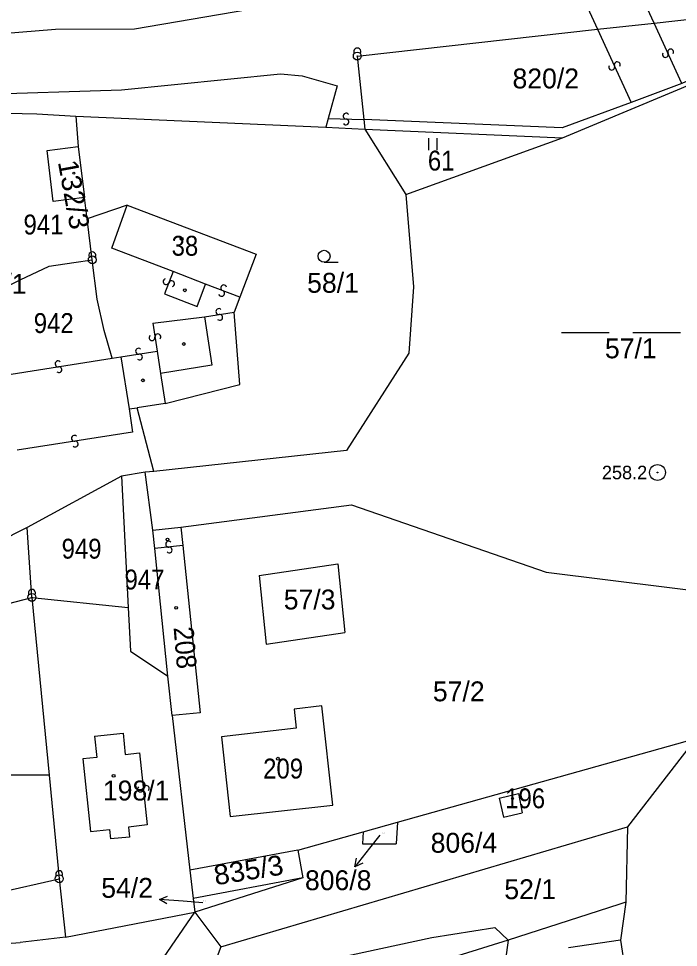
# Model space of a CAD drawing. Extents: x -680102 to -677253, y -1007548 to -1006096.
# Drawn here: x -679840 to -679757, y -1007209.6 to -1007092.8 of the extents above; entities that cross this region are included whole.
import ezdxf
from ezdxf.enums import TextEntityAlignment as Align

# ---------------------------------------------------------------- set-up
doc = ezdxf.new("R2010")
doc.units = 0
for name, color, linetype, lineweight in [('1', 7, 'Continuous', 25), ('16', 7, 'Continuous', 25), ('24', 7, 'Continuous', 25), ('25', 7, 'Continuous', 25), ('4', 7, 'Continuous', 25)]:
    doc.layers.add(name, color=color, linetype=linetype, lineweight=lineweight)
for name, color, linetype in [('17', 7, 'Continuous'), ('18', 7, 'Continuous'), ('19', 7, 'Continuous')]:
    doc.layers.add(name, color=color, linetype=linetype)

msp = doc.modelspace()

# ---------------------------------------------------------------- linework, layer by layer
at = {"layer": '1'}
for p, q in [((-679771.61, -1007107.84), (-679749.26, -1007098.51)), ((-679832.79, -1007105.1), (-679832.48, -1007108.92)), ((-679796.44, -1007106.73), (-679771.61, -1007107.84)), ((-679791.3, -1007114.95), (-679790.34, -1007126.57)), ((-679826.31, -1007116.31), (-679831.35, -1007118.02)), ((-679826.31, -1007116.31), (-679810.11, -1007122.46)), ((-679810.11, -1007122.46), (-679812.17, -1007127.87)), ((-679812.17, -1007127.87), (-679812.88, -1007129.74)), ((-679812.17, -1007138.86), (-679812.88, -1007129.74)), ((-679828.21, -1007135.56), (-679829.22, -1007132.08)), ((-679821.54, -1007141.26), (-679812.17, -1007138.86)), ((-679821.54, -1007141.26), (-679825.07, -1007141.78)), ((-679826.07, -1007141.93), (-679825.07, -1007141.78)), ((-679822.97, -1007149.78), (-679825.07, -1007141.78)), ((-679798.77, -1007147.16), (-679822.97, -1007149.78)), ((-679822.97, -1007149.78), (-679824.08, -1007149.88)), ((-679827.02, -1007150.37), (-679838.89, -1007156.83)), ((-679838.89, -1007156.83), (-679844.73, -1007159.74)), ((-679838.3, -1007165.62), (-679838.89, -1007156.83)), ((-679822.84, -1007159.48), (-679823.08, -1007157.16)), ((-679821.2, -1007175.52), (-679822.84, -1007159.48)), ((-679838.3, -1007165.62), (-679826.2, -1007166.88)), ((-679825.92, -1007172.38), (-679821.2, -1007175.52)), ((-679820.69, -1007180.49), (-679821.2, -1007175.52)), ((-679820.69, -1007180.49), (-679818.43, -1007199.94)), ((-679754.82, -1007183.38), (-679763.43, -1007194.48)), ((-679836.13, -1007187.98), (-679845.34, -1007188)), ((-679792.33, -1007193.89), (-679792.52, -1007196.61)), ((-679814.54, -1007209.57), (-679763.43, -1007194.48)), ((-679796.64, -1007195.1), (-679796.74, -1007196.61)), ((-679796.74, -1007196.61), (-679792.52, -1007196.61)), ((-679804.87, -1007197.41), (-679818.43, -1007199.94)), ((-679834.87, -1007201), (-679834.08, -1007208.34)), ((-679804.25, -1007200.87), (-679818.02, -1007203.49)), ((-679764.51, -1007204.23), (-679778.42, -1007208.71)), ((-679763.64, -1007203.94), (-679764.51, -1007204.23)), ((-679834.08, -1007208.34), (-679817.82, -1007205.22)), ((-679817.82, -1007205.22), (-679814.54, -1007209.57)), ((-679842.65, -1007209.24), (-679839.8, -1007209.02)), ((-679834.08, -1007208.34), (-679839.8, -1007209.02)), ((-679778.42, -1007208.71), (-679803.8, -1007216.62)), ((-679764.29, -1007208.71), (-679770.85, -1007209.71)), ((-679764.29, -1007208.71), (-679763.02, -1007217.57)), ((-679814.54, -1007209.57), (-679816.78, -1007215.35))]:
    msp.add_line(p, q, dxfattribs=at)
for points in [[(-679974.97, -1007077.43), (-679941.96, -1007088.72), (-679930.57, -1007092.28), (-679915.66, -1007095.94), (-679902.15, -1007098.5), (-679887.23, -1007100.52), (-679863.69, -1007102.17), (-679845.48, -1007102.38), (-679827.03, -1007101.79), (-679807.03, -1007099.79), (-679804.33, -1007100.05), (-679799.92, -1007101.29), (-679801.05, -1007105.4), (-679801.35, -1007106.51)], [(-679846.67, -1007095.09), (-679835.35, -1007094.16), (-679825.42, -1007094.12), (-679811.14, -1007091.68)], [(-679797.39, -1007097.55), (-679767.18, -1007094.19), (-679760.09, -1007093.4), (-679751.9, -1007092.49)], [(-679797.39, -1007097.55), (-679796.56, -1007105.54), (-679796.44, -1007106.73)], [(-679850.5, -1007104.53), (-679837.67, -1007104.82), (-679832.79, -1007105.1)], [(-679832.79, -1007105.1), (-679801.35, -1007106.51), (-679796.44, -1007106.73)], [(-679796.44, -1007106.73), (-679791.3, -1007114.95), (-679771.61, -1007107.84)], [(-679830.71, -1007123.18), (-679831.35, -1007118.02), (-679831.68, -1007115.35)], [(-679843.19, -1007127.35), (-679839.76, -1007125.71), (-679836.14, -1007123.99), (-679833.05, -1007123.53), (-679830.71, -1007123.18)], [(-679829.22, -1007132.08), (-679830.09, -1007128.13), (-679830.71, -1007123.18)], [(-679790.34, -1007126.57), (-679790.93, -1007134.9), (-679798.77, -1007147.16)], [(-679828.21, -1007135.56), (-679827.13, -1007135.39), (-679826.07, -1007141.93)], [(-679823.08, -1007157.16), (-679824.08, -1007149.88), (-679827.02, -1007150.37)], [(-679827.02, -1007150.37), (-679826.2, -1007166.88), (-679825.92, -1007172.38)], [(-679819.56, -1007156.8), (-679798.14, -1007154), (-679773.64, -1007162.47)], [(-679823.08, -1007157.16), (-679819.56, -1007156.8), (-679819.32, -1007159.12), (-679817.17, -1007180.13), (-679820.69, -1007180.49)], [(-679809.74, -1007162.89), (-679799.85, -1007161.42), (-679798.98, -1007170.03)], [(-679773.64, -1007162.47), (-679742.99, -1007166.28), (-679745.38, -1007171.78)], [(-679809.74, -1007162.89), (-679808.87, -1007171.5), (-679798.98, -1007170.03)], [(-679853.64, -1007188.02), (-679853.67, -1007169.64), (-679838.3, -1007165.62)], [(-679838.3, -1007165.62), (-679836.13, -1007187.98), (-679834.87, -1007201)], [(-679804.87, -1007197.41), (-679796.64, -1007195.1), (-679792.33, -1007193.89), (-679754.82, -1007183.38)], [(-679779.56, -1007190.89), (-679777.14, -1007190.3), (-679776.67, -1007192.71)], [(-679779.56, -1007190.89), (-679779.01, -1007193.25), (-679776.67, -1007192.71)], [(-679763.43, -1007194.48), (-679763.64, -1007203.94), (-679764.29, -1007208.71)], [(-679804.87, -1007197.41), (-679804.25, -1007200.87), (-679817.82, -1007205.22)], [(-679818.43, -1007199.94), (-679818.02, -1007203.49), (-679817.82, -1007205.22)], [(-679835.43, -1007221.28), (-679829.74, -1007223.55), (-679826.64, -1007218.02), (-679817.82, -1007205.22)], [(-679804.53, -1007211.96), (-679788.01, -1007208.4), (-679780.11, -1007207.15), (-679778.42, -1007208.71)], [(-679778.42, -1007208.71), (-679779.12, -1007213.98), (-679775.35, -1007216.63)]]:
    msp.add_lwpolyline(points, dxfattribs=at)
for points in [[(-679836.37, -1007109.44), (-679832.48, -1007108.92), (-679831.68, -1007115.35), (-679835.62, -1007115.86)], [(-679814.48, -1007183.16), (-679813.36, -1007193.19), (-679800.48, -1007191.75), (-679801.87, -1007179.28), (-679805.35, -1007179.67), (-679805.08, -1007182.05)]]:
    msp.add_lwpolyline(points, close=True, dxfattribs=at)
at = {"layer": '16'}
for p, q in [((-679794.55, -1007195.51), (-679795.85, -1007197.16)), ((-679795.85, -1007197.16), (-679797.705, -1007199.517)), ((-679819.29, -1007203.84), (-679822.28, -1007203.6)), ((-679816.82, -1007204.03), (-679819.29, -1007203.84))]:
    msp.add_line(p, q, dxfattribs=at)
for points in [[(-679796.693, -1007199.04), (-679797.705, -1007199.517), (-679797.479, -1007198.422)], [(-679821.323, -1007204.177), (-679822.28, -1007203.6), (-679821.243, -1007203.182)]]:
    msp.add_lwpolyline(points, dxfattribs=at)
at = {"layer": '24'}
for centre, radius in [((-679797.39, -1007097.55), 0.5), ((-679797.39, -1007097.55), 0.022), ((-679830.71, -1007123.18), 0.5), ((-679830.71, -1007123.18), 0.022), ((-679759.65, -1007149.92), 1), ((-679759.65, -1007149.92), 0.032), ((-679838.3, -1007165.62), 0.5), ((-679838.3, -1007165.62), 0.022), ((-679834.87, -1007201), 0.5), ((-679834.87, -1007201), 0.022)]:
    msp.add_circle(centre, radius, dxfattribs=at)
for centre in [(-679797.391, -1007096.987), (-679830.711, -1007122.617), (-679838.301, -1007165.057), (-679834.871, -1007200.437)]:
    msp.add_arc(centre, 0.437, 328.35109, 209.97456, dxfattribs=at)
at = {"layer": '25'}
for p, q in [((-679788.397, -1007109.395), (-679788.397, -1007107.895)), ((-679787.363, -1007109.395), (-679787.363, -1007107.895)), ((-679801.57, -1007123.48), (-679799.82, -1007123.48)), ((-679771.74, -1007132.3), (-679765.74, -1007132.3)), ((-679762.74, -1007132.3), (-679756.74, -1007132.3))]:
    msp.add_line(p, q, dxfattribs=at)
for centre, radius in [((-679833.03, -1007112.29), 0.122), ((-679819.48, -1007120.52), 0.175), ((-679801.57, -1007122.73), 0.75), ((-679819.08, -1007127.01), 0.175), ((-679819.2, -1007133.76), 0.175), ((-679824.34, -1007138.33), 0.175), ((-679821.27, -1007158.35), 0.175), ((-679820.18, -1007166.95), 0.175), ((-679807.37, -1007185.91), 0.175), ((-679828.03, -1007188.07), 0.175), ((-679777.89, -1007190.92), 0.122)]:
    msp.add_circle(centre, radius, dxfattribs=at)
for centre, radius, start, end in [((-679758.665, -1007097.352), 0.367, 152.60843, 24.40548), ((-679757.994, -1007097.049), 0.368, 332.32384, 204.20386), ((-679764.724, -1007098.65), 0.368, 331.73818, 204.05897), ((-679765.397, -1007098.95), 0.369, 151.8373, 23.70792), ((-679798.796, -1007105.103), 0.368, 35.41611, 267.81752), ((-679798.825, -1007105.838), 0.369, 215.62962, 87.66941), ((-679821.432, -1007125.924), 0.368, 106.56598, 338.31691), ((-679820.748, -1007126.194), 0.368, 286.24219, 158.60538), ((-679814.174, -1007126.708), 0.368, 16.56526, 248.52282), ((-679814.444, -1007127.392), 0.368, 196.39934, 68.60466), ((-679814.805, -1007129.676), 0.368, 46.42521, 278.59455), ((-679814.697, -1007130.404), 0.368, 226.43115, 98.55446), ((-679823.195, -1007132.962), 0.368, 136.32306, 8.02566), ((-679822.466, -1007132.856), 0.368, 316.01893, 188.43988), ((-679824.895, -1007134.666), 0.368, 46.42521, 278.59455), ((-679835.014, -1007136.256), 0.368, 46.48128, 278.44059), ((-679824.787, -1007135.394), 0.368, 226.43115, 98.55446), ((-679834.908, -1007136.985), 0.368, 226.32378, 98.293), ((-679832.962, -1007145.615), 0.368, 46.32234, 278.11034), ((-679832.856, -1007146.344), 0.368, 226.29739, 98.43916), ((-679821.113, -1007158.933), 0.368, 43.13147, 274.87893), ((-679821.046, -1007159.666), 0.367, 222.8967, 95.30809), ((-679824.657, -1007189.725), 0.368, 133.35192, 5.09045), ((-679823.924, -1007189.654), 0.367, 313.49859, 185.61906)]:
    msp.add_arc(centre, radius, start, end, dxfattribs=at)
at = {"layer": '4'}
for p, q in [((-679801.05, -1007105.4), (-679796.56, -1007105.54)), ((-679827.13, -1007135.39), (-679822.56, -1007134.67)), ((-679841.72, -1007137.67), (-679828.21, -1007135.56)), ((-679826.07, -1007141.93), (-679825.65, -1007144.85)), ((-679825.65, -1007144.85), (-679840.16, -1007147.11)), ((-679819.32, -1007159.12), (-679822.84, -1007159.48)), ((-679854.02, -1007205.35), (-679834.87, -1007201))]:
    msp.add_line(p, q, dxfattribs=at)
for points in [[(-679756.57, -1007101), (-679760.09, -1007093.4), (-679764.49, -1007083.92)], [(-679771.41, -1007084.97), (-679767.18, -1007094.19), (-679762.95, -1007103.4)], [(-679734.78, -1007090.98), (-679756.57, -1007101), (-679762.95, -1007103.4), (-679771.63, -1007106.59), (-679796.56, -1007105.54)], [(-679812.17, -1007127.87), (-679816.46, -1007126.23), (-679820.56, -1007124.66), (-679828.25, -1007121.73), (-679826.31, -1007116.31)], [(-679820.56, -1007124.66), (-679821.63, -1007127.46), (-679817.53, -1007129.04), (-679816.46, -1007126.23)], [(-679823.11, -1007131.14), (-679816.61, -1007130.33), (-679812.88, -1007129.74)], [(-679823.11, -1007131.14), (-679822.56, -1007134.67), (-679822.12, -1007137.49), (-679821.54, -1007141.26)], [(-679816.61, -1007130.33), (-679815.68, -1007136.44), (-679822.12, -1007137.49)], [(-679830.42, -1007183.06), (-679830.13, -1007185.74), (-679831.92, -1007185.93), (-679830.95, -1007195.07), (-679828.55, -1007194.8), (-679828.42, -1007196)], [(-679830.42, -1007183.06), (-679826.84, -1007182.68), (-679826.56, -1007185.36), (-679824.77, -1007185.17)], [(-679824.77, -1007185.17), (-679823.81, -1007194.21), (-679826.15, -1007194.51), (-679826.02, -1007195.78), (-679828.42, -1007196)]]:
    msp.add_lwpolyline(points, dxfattribs=at)

# ---------------------------------------------------------------- texts
at = {"layer": '16'}
for s, p in [('806/8', (-679795.61, -1007202.44)), ('54/2', (-679823.08, -1007203.4))]:
    msp.add_text(s, height=2.5, dxfattribs=at).set_placement(p, align=Align.RIGHT)
at = {"layer": '17'}
msp.add_text('258.2', height=1.7, dxfattribs=at).set_placement((-679760.95, -1007150.77), align=Align.RIGHT)
at = {"layer": '18'}
for s, height, p in [('820/2', 2.5, (-679777.88, -1007101.62)), ('58/1', 2.5, (-679803.7, -1007127.32)), ('57/1', 2.5, (-679766.26, -1007135.56)), ('57/3', 2.5, (-679806.64, -1007167.14)), ('57/2', 2.5, (-679787.89, -1007178.69)), ('806/8', 0.1, (-679794.35, -1007195.31)), ('806/4', 2.5, (-679788.17, -1007197.73)), ('52/1', 2.5, (-679778.91, -1007203.57))]:
    msp.add_text(s, height=height, dxfattribs=at).set_placement(p)
at = {"layer": '18', "width": 0.9}
for s, p in [('61', (-679788.52, -1007111.95)), ('941', (-679839.36, -1007119.99)), ('942', (-679838.07, -1007132.38))]:
    msp.add_text(s, height=2.5, dxfattribs=at).set_placement(p)
for s, p in [('949', (-679832.059, -1007160.75)), ('947', (-679824.15, -1007164.63))]:
    msp.add_text(s, height=2.5, dxfattribs=at).set_placement(p, align=Align.CENTER)
at = {"layer": '18', "width": 1.05}
msp.add_text('835/3', height=2.5, rotation=9.1, dxfattribs=at).set_placement((-679810.873, -1007201.137), align=Align.CENTER)
at = {"layer": '18'}
msp.add_text('54/2', height=0.1, dxfattribs=at).set_placement((-679816.62, -1007203.83), align=Align.CENTER)
at = {"layer": '19'}
for s, rotation, width, p in [('132/3', 280.402, 1.05, (-679835.048, -1007110.87)), ('208', 274.802, 0.95, (-679820.494, -1007169.412))]:
    msp.add_text(s, height=2.5, rotation=rotation, dxfattribs=dict(at, width=width)).set_placement(p)
at = {"layer": '19', "width": 0.9}
for s, p in [('38', (-679820.74, -1007122.66)), ('209', (-679809.23, -1007188.4)), ('196', (-679778.8, -1007192.14))]:
    msp.add_text(s, height=2.5, dxfattribs=at).set_placement(p)
at = {"layer": '19'}
for s, p in [('132/1', (-679847.34, -1007127.44)), ('198/1', (-679829.38, -1007191.16))]:
    msp.add_text(s, height=2.5, dxfattribs=at).set_placement(p)

doc.saveas('drawing.dxf')
